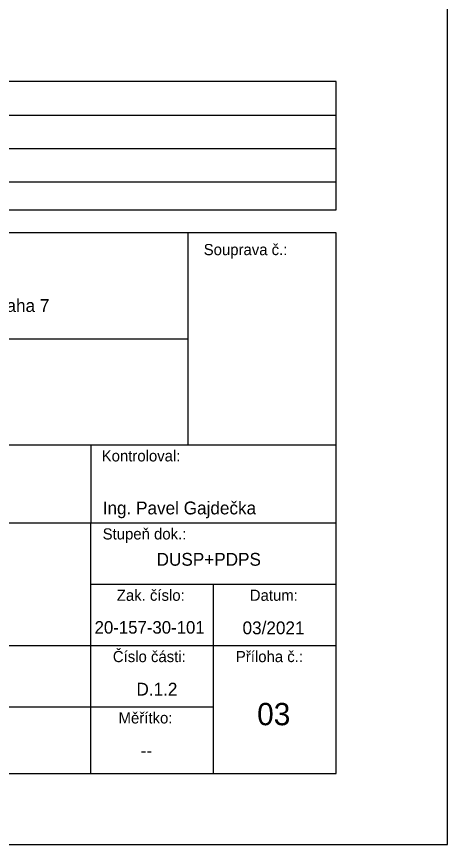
# Model space of a CAD drawing. Extents: x 563 to 1437, y -18 to 279.
# Drawn here: x 1181 to 1258.3, y -18.3 to 130.2 of the extents above; entities that cross this region are included whole.
import ezdxf

# ---------------------------------------------------------------- set-up
doc = ezdxf.new("R2010")
doc.units = 0
doc.layers.add('ROZPISKA', color=7, linetype='Continuous')

msp = doc.modelspace()

# ---------------------------------------------------------------- linework, layer by layer
msp.add_lwpolyline([(563.37, 278.7), (563.37, -18.3), (1258.3, -18.3), (1258.3, 278.7)], close=True)
at = {"layer": 'ROZPISKA'}
for p, q in [((1068.34, 112.54), (1238.34, 112.54)), ((1068.34, 106.54), (1238.34, 106.54)), ((1068.34, 100.54), (1238.34, 100.54)), ((1068.34, 53.4), (1238.34, 53.4)), ((1194.34, 53.4), (1194.34, 39.4)), ((1068.34, 39.4), (1238.34, 39.4)), ((1194.34, -5.6), (1194.34, 39.4)), ((1194.34, 28.4), (1238.34, 28.4)), ((1216.34, -5.6), (1216.34, 28.4)), ((1068.34, 17.4), (1238.34, 17.4)), ((1068.34, 6.4), (1216.34, 6.4))]:
    msp.add_line(p, q, dxfattribs=at)
for points in [[(1068.34, 95.54), (1238.34, 95.54), (1238.34, 118.54), (1068.34, 118.54)], [(1238.34, -5.6), (1238.34, 91.4), (1068.34, 91.4), (1068.34, -5.6)]]:
    msp.add_lwpolyline(points, close=True, dxfattribs=at)
for points in [[(1211.77, 53.4), (1211.77, 91.4)], [(1068.34, 72.4), (1211.77, 72.4)]]:
    msp.add_lwpolyline(points, dxfattribs=at)

# ---------------------------------------------------------------- texts
for s, height, p in [('Souprava č.:', 2, (1214.57, 87.4)), ('Oblastní ředitelství Praha, Partyzánská 24, 170 00 Praha 7', 2.3, (1106.7, 77.21)), ('Kontroloval:', 2, (1196.27, 50.4)), ('Ing. Pavel Gajdečka', 2.3, (1196.45, 40.9)), ('Stupeň dok.:', 2, (1196.44, 36.4)), ('DUSP+PDPS', 2.3, (1206.12, 31.69)), ('Zak. číslo:', 2, (1198.98, 25.4)), ('Datum:', 2, (1222.84, 25.4)), ('20-157-30-101', 2.25, (1195, 19.51)), ('03/2021', 2.3, (1221.54, 19.4)), ('Číslo části:', 2, (1198.27, 14.4)), ('Příloha č.:', 2, (1220.34, 14.4)), ('D.1.2', 2.3, (1202.5, 8.4)), ('03', 4, (1224.16, 3.08)), ('Měřítko:', 2, (1199.3, 3.4)), ('--', 2.3, (1203.27, -2.6))]:
    msp.add_text(s, height=height, dxfattribs=at).set_placement(p)

doc.saveas('drawing.dxf')
